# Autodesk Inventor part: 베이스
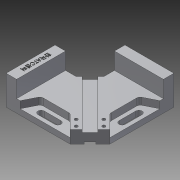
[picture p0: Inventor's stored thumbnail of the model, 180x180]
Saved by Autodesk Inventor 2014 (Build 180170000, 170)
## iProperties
Created: 2019-04
Part Number: 베이스
Material: Aluminum 6061
Document SubType Name: Modeling
Designer: kh
Density: 2.71 g/cm^3
Appearance: Aluminum - Flat
Mass: 603.684 g
Surface Area: 426.592 cm^2
Volume: 222.762 cm^3
Author: kh
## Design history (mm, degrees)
sketch "Sketch1"
  geometry: L1 (-60, 60)-(60, 60); L2 (60, 60)-(60, -60); L3 (60, -60)-(-60, -60); L4 (-60, -60)-(-60, 60); L5 (-60, 60)-(60, -60); L6 (60, 60)-(-60, -60); L7 (60, -60)-(45.858, -45.858); L8 (45.858, -45.858)-(31.716, -60); L9 (45.858, -45.858)-(60, -31.716); 1 further point
  constraints: 18 end point, 3 equal length, 3 point on line, 2 midpoint, 2 perpendicular, 1 horizontal
  dimensions: "d5" = 120 distance of L2.end L3.end; "d6" = 120 distance of L1.end L2.end; "d7" = 20 distance of L2.end L7.end
extrude "Extrusion1" new body sketch "Sketch1" distance "d8" = 18; taper "d9" = 0 deg
sketch "Sketch2"
  geometry: L1 (-60, 60)-(-60, -60) reference; L2 (31.716, -60)-(60, -31.716) reference; L3 (60, 60)-(-60, 60) reference; L4 (45.858, -45.858)-(-19.903, 19.903); L5 (-60, 60)-(-60, 10); L6 (-60, 60)-(-10, 60); L7 (-19.903, 19.903)-(-44.384, -4.578); L8 (-19.903, 19.903)-(6.453, 46.259); L9 (-60, 10)-(-29.806, 10); L10 (-10, 60)-(-10, 29.806); 1 further point
  constraints: 14 end point, 4 point on line, 3 perpendicular, 1 collinear, 1 midpoint, 1 parallel
  dimensions: "d10" = 93 distance of L4.start L4.end; "d11" = 50 distance of L1.start L5.end; "d12" = 50 distance of L1.start L6.end
extrude "Extrusion2" cut sketch "Sketch2" stored distance "d13" = 18; taper "d14" = 0 deg
sketch "Sketch3"
  geometry: L1 (-29.806, 10)-(-60, 10) reference; L2 (60, -31.716)-(60, 60) reference; L3 (-60, -60)-(-45, -60); L4 (-45, -60)-(-45, 10); L5 (-45, 10)-(-60, 10); L6 (-60, 10)-(-60, -60); L7 (-10, 60)-(60, 60); L8 (60, 60)-(60, 45); L9 (60, 45)-(-10, 45); L10 (-10, 45)-(-10, 60); 1 further point
  constraints: 16 end point, 4 parallel, 2 horizontal, 2 perpendicular, 2 point on line
  dimensions: "d15" = 15 distance of L5.end L4.end; "d16" = 15 distance of L7.end L8.end
extrude "Extrusion3" join sketch "Sketch3" distance "d17" = 24; taper "d18" = 0 deg
sketch "Sketch4"
  geometry: L1 (31.716, -60)-(60, -31.716) reference; L2 (-10, 29.806)-(-29.806, 10) reference; L3 (-25.56, 14.246)-(40.201, -51.515); L4 (-14.246, 25.56)-(51.515, -40.201); L5 (0, 0)-(45.858, -45.858); L6 (-25.56, 14.246)-(-14.246, 25.56); L7 (40.201, -51.515)-(51.515, -40.201)
  constraints: 10 end point, 4 point on line, 2 perpendicular, 1 collinear, 1 midpoint, 1 parallel, 1 other
  dimensions: "d19" = 16 distance of L3.end L4.end
extrude "Extrusion4" cut sketch "Sketch4" distance "d20" = 3.5; taper "d21" = 0 deg
sketch "Sketch5"
  geometry: L1 (-31.716, -60)-(-60, -31.716) reference; L2 (29.806, 10)-(10, 29.806) reference; L3 (0, 0)-(-45.858, -45.858); L4 (-50.101, -41.615)-(15.66, 24.146); L5 (-41.615, -50.101)-(24.146, 15.66); L6 (15.66, 24.146)-(24.146, 15.66); L7 (-50.101, -41.615)-(-41.615, -50.101)
  constraints: 10 end point, 4 point on line, 2 collinear, 2 perpendicular, 1 midpoint, 1 other
  dimensions: "d22" = 12 distance of L4.start L5.start
extrude "Extrusion5" cut sketch "Sketch5" distance "d23" = 3; taper "d24" = 0 deg
sketch "Sketch6"
  geometry: L1 (-45, -60)-(31.716, -60) reference; L2 (31.716, -60)-(40.201, -51.515) reference; L3 (-45, -60)-(-40, -60); L4 (-40, -60)-(-30, -40); L5 (-30, -40)-(7.321, -40); L6 (31.716, -60)-(11.716, -40); L7 (-30, -40)-(11.716, -40); L8 (-60, 10)-(-60, -60) reference; L9 (-45, 10)-(-60, 10) reference; L10 (-60, 10)-(-60, -60) reference; L11 (-60, -60)-(-45, -60) reference; L12 (-45, -60)-(-45, 10) reference; L13 (-60, -60)-(-45, -60) reference; L14 (-20, -50)-(4, -50); L15 (-20, -52.25)-(4, -52.25); L16 (4, -47.75)-(-20, -47.75); L17 (-9.142, -40)-(-9.142, -60); A1 r 2.25 centre (-20, -50) between (-20, -47.75) and (-20, -52.25); A2 r 2.25 centre (4, -50) between (4, -52.25) and (4, -47.75); 2 further points
  constraints: 20 end point, 4 point on circle, 4 tangent, 3 parallel, 2 centre point, 2 midpoint, 2 perpendicular, 2 point on line, 1 collinear
  dimensions: "d25" = 5 distance of L1.start L3.end; "d26" = 30 horizontal distance of L4.end L8.end; "d30" = 20 vertical distance of L4.end L3.end; "d31" = 24 distance of L14.start L14.end; "d32" = 4.5 diameter of A2; "d33" = 40 horizontal distance of L14.start L8.end; "d34" = 10 vertical distance of L8.end L14.start
extrude "Extrusion6" cut sketch "Sketch6" distance "d35" = 10; taper "d36" = 0 deg
sketch "Sketch7"
  geometry: L1 (4, -47.75)-(-20, -47.75) reference; L2 (-20, -52.25)-(4, -52.25) reference; A1 r 2.25 centre (4, -50) between (4, -52.25) and (4, -47.75) reference; A2 r 2.25 centre (-20, -50) between (-20, -47.75) and (-20, -52.25) reference; 1 further point
extrude "Extrusion7" cut sketch "Sketch7" stored distance "d37" = 10; taper "d38" = 0 deg
sketch "Sketch8"
  geometry: L1 (60, -31.716)-(60, 45) reference; L2 (-10, 45)-(-10, 29.806) reference; L3 (-10, 29.806)-(-14.246, 25.56) reference; L4 (60, -31.716)-(40, -11.716); L5 (40, -11.716)-(40, 30); L6 (40, 30)-(60, 40); L7 (60, 45)-(60, 60) reference; L8 (60, 60)-(-10, 60) reference; L9 (-10, 60)-(-10, 45) reference; L10 (-10, 45)-(60, 45) reference; 1 further point
  constraints: 6 end point, 1 parallel, 1 perpendicular, 1 point on line
  dimensions: "d39" = 20 distance of L7.end L6.end; "d40" = 30 vertical distance of L5.end L7.end; "d41" = 20 horizontal distance of L5.end L7.end
extrude "Extrusion8" cut sketch "Sketch8" distance "d42" = 10; taper "d43" = 0 deg
sketch "Sketch9"
  geometry: L1 (60, 40)-(60, -31.716) reference; L2 (50, -4)-(50, 20); L3 (52.25, -4)-(52.25, 20); L4 (47.75, 20)-(47.75, -4); L5 (60, 45)-(60, 60) reference; L6 (60, 60)-(-10, 60) reference; L7 (-10, 60)-(-10, 45) reference; L8 (-10, 45)-(60, 45) reference; A1 r 2.25 centre (50, -4) between (47.75, -4) and (52.25, -4); A2 r 2.25 centre (50, 20) between (52.25, 20) and (47.75, 20); 2 further points
  constraints: 8 end point, 4 point on circle, 4 tangent, 2 centre point, 2 parallel, 1 midpoint
  dimensions: "d44" = 24 distance of L2.start L2.end; "d45" = 4.5 diameter of A2; "d46" = 40 vertical distance of L2.end L5.end; "d47" = 10 horizontal distance of L5.end L2.end
extrude "Extrusion9" cut sketch "Sketch9" stored distance "d48" = 10; taper "d49" = 0 deg
sketch "Sketch10"
  geometry: L1 (11.716, -40)-(31.716, -60) reference; L2 (31.716, -60)-(40.201, -51.515) reference; C1 r 2.25 at (31.716, -51.515); C2 r 2.25 at (23.23, -43.029); 1 further point
  constraints: 2 centre point
  dimensions: "d50" = 4.5 diameter of C1; "d51" = 4.5 diameter of C2; "d52" = 6 distance from line of C1.centre L2; "d53" = 6 distance from line of C1.centre L1; "d54" = 12 distance of C2.centre C1.centre; "d55" = 6 distance from line of C2.centre L1
extrude "Extrusion10" cut sketch "Sketch10" stored distance "d56" = 10; taper "d57" = 0 deg
sketch "Sketch11"
  geometry: L1 (-14.246, 25.56)-(51.515, -40.201) reference; L2 (51.515, -40.201)-(60, -31.716) reference; L3 (60, -31.716)-(40, -11.716) reference; C1 r 2.25 at (51.515, -31.716); C2 r 2.25 at (43.029, -23.23); 1 further point
  constraints: 2 centre point
  dimensions: "d58" = 4.5 diameter of C1; "d59" = 4.5 diameter of C2; "d60" = 6 distance from line of C1.centre L2; "d61" = 6 distance from line of C1.centre L3; "d62" = 12 distance of C1.centre C2.centre; "d63" = 6 distance from line of C2.centre L1
extrude "Extrusion11" cut sketch "Sketch11" stored distance "d64" = 10; taper "d65" = 0 deg
sketch "Sketch12"
  geometry: C1 r 2.25 at (-31.716, -51.515) reference; C2 r 2.25 at (-23.23, -43.029) reference; C3 r 4 at (-31.716, -51.515); C4 r 4 at (-23.23, -43.029); 1 further point
  constraints: 2 centre point, 2 coincident
  dimensions: "d66" = 8 diameter of C3; "d67" = 8 diameter of C4
extrude "Extrusion12" cut sketch "Sketch12" distance "d68" = 10; taper "d69" = 0 deg
sketch "Sketch13"
  geometry: C1 r 2.25 at (-51.515, -31.716) reference; C2 r 2.25 at (-43.029, -23.23) reference; C3 r 4 at (-51.515, -31.716); C4 r 4 at (-43.029, -23.23); 1 further point
  constraints: 2 centre point, 2 coincident
  dimensions: "d70" = 8 diameter of C3; "d71" = 8 diameter of C4
extrude "Extrusion13" cut sketch "Sketch13" distance "d72" = 10; taper "d73" = 0 deg
sketch "Sketch14"
  geometry: L1 (-20, -52.25)-(4, -52.25) reference; L2 (4, -47.75)-(-20, -47.75) reference; L3 (-20, -50)-(4, -50); L4 (-20, -54.5)-(4, -54.5); L5 (4, -45.5)-(-20, -45.5); A1 r 2.25 centre (4, -50) between (4, -52.25) and (4, -47.75) reference; A2 r 2.25 centre (-20, -50) between (-20, -47.75) and (-20, -52.25) reference; A3 r 4.5 centre (-20, -50) between (-20, -45.5) and (-20, -54.5); A4 r 4.5 centre (4, -50) between (4, -54.5) and (4, -45.5); 2 further points
  constraints: 8 end point, 4 point on circle, 4 tangent, 2 centre point, 2 parallel, 1 midpoint
  dimensions: "d74" = 9 distance between parallel lines of L4 L5
extrude "Extrusion14" cut sketch "Sketch14" stored distance "d75" = 10; taper "d76" = 0 deg
sketch "Sketch15"
  geometry: L1 (52.25, 20)-(52.25, -4) reference; L2 (47.75, -4)-(47.75, 20) reference; L3 (50, -4)-(50, 20); L4 (54.5, -4)-(54.5, 20); L5 (45.5, 20)-(45.5, -4); A1 r 2.25 centre (50, 20) between (52.25, 20) and (47.75, 20) reference; A2 r 2.25 centre (50, -4) between (47.75, -4) and (52.25, -4) reference; A3 r 4.5 centre (50, -4) between (45.5, -4) and (54.5, -4); A4 r 4.5 centre (50, 20) between (54.5, 20) and (45.5, 20); 2 further points
  constraints: 8 end point, 4 point on circle, 4 tangent, 2 centre point, 2 parallel, 1 midpoint
  dimensions: "d77" = 9 distance between parallel lines of L5 L4
extrude "Extrusion15" cut sketch "Sketch15" stored distance "d78" = 10; taper "d79" = 0 deg
sketch "Sketch16"
  geometry: L1 (-45, 10)-(-60, 10) reference; L2 (-45, -60)-(-45, 10) reference; L3 (-49.498, -4.261)-(-49.498, -45.739); L4 (-49.498, -45.739)-(-55.502, -45.739); L5 (-55.502, -45.739)-(-55.502, -4.261); L6 (-55.502, -4.261)-(-49.498, -4.261); L7 (-49.498, -4.261)-(-55.502, -45.739); 2 further points
  constraints: 2 end point, 1 midpoint, 2 other
  dimensions: "d80" = 35 distance from line of L1 point (-52.5, -25); "d81" = 7.5 distance from line of point (-52.5, -25) L2
emboss "Emboss1" sketch "Sketch16" dims "d10" = 93, "d11" = 50, "d12" = 50, "d82" = 0.5, "d83" = 0
fillet "Fillet1" dims "d84" = 5
body "Solid1"
node "Projected Loop1"
node "Projected Loop2"
node "Projected Loop3"
